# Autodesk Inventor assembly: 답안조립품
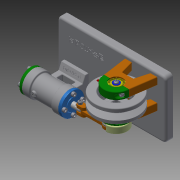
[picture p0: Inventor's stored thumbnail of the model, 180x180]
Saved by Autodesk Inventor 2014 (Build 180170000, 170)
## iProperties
Created: 2018-01
Part Number: 답안조립품
Document SubType Name: Assembly
Designer: kb542
Author: kb542
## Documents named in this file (19)
- C:\Users\kb542\Desktop\380107V1005\답안조립품.iam
- C:\Users\kb542\Desktop\380107V1005\플레이트.ipt
- C:\Users\kb542\Desktop\380107V1005\3mm 와셔.ipt
- C:\Users\kb542\Desktop\380107V1005\둥근머리볼트 M3x12.ipt
- C:\Users\kb542\Desktop\380107V1005\크랭크축.ipt
- C:\Users\kb542\Desktop\380107V1005\플랜지.ipt
- C:\Users\kb542\Desktop\380107V1005\하우징커버-A.ipt
- C:\Users\kb542\Desktop\380107V1005\커넥팅로드-A.ipt
- C:\Users\kb542\Desktop\380107V1005\베어링 8x22x7.ipt
- C:\Users\kb542\Desktop\380107V1005\V-벨트풀리.ipt
- C:\Users\kb542\Desktop\380107V1005\스페이서.ipt
- C:\Users\kb542\Desktop\380107V1005\지지대-A.ipt
- C:\Users\kb542\Desktop\380107V1005\베어링커버-A.ipt
- C:\Users\kb542\Desktop\380107V1005\볼트 M3x8.ipt
- C:\Users\kb542\Desktop\380107V1005\볼트 M3x12.ipt
- C:\Users\kb542\Desktop\380107V1005\하우징.ipt
- C:\Users\kb542\Desktop\380107V1005\하우징커버-B.ipt
- C:\Users\kb542\Desktop\380107V1005\커넥팅로드-B.ipt
- C:\Users\kb542\Desktop\380107V1005\피스톤.ipt
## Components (9 placed, 8 different names)
1. 플레이트:1
2. 3mm 와셔:1
3. 플랜지:1
4. 하우징커버-A:1
5. V-벨트풀리:1 — 각도:1
6. 하우징:1
7. 하우징커버-B:1
8. 피스톤:1
9. 3mm 와셔:2
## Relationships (1: Angle 1)
- 각도:1 [Angle]: V-벨트풀리:1
